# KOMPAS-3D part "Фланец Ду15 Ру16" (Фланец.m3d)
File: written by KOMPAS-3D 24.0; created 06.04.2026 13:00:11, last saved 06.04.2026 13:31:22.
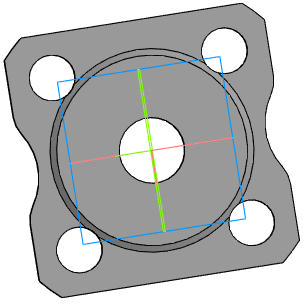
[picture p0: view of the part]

Document properties: Автор: R2D2; Полное имя файла: E:\Работа\Зайцев\Солянка\VSR1-13V-PED-F Клапан запорно-регулирующий DN.ru\DN20\исходные материалы\Фланец.m3d

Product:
- Component [standard]: (unnamed)  | qty 1  | Материал: ВЧ40 ГОСТ 7293-85 (density 7200 kg/m3); Масса: 0.86; additional columns: 20-16-01-1-B-ВЧ40-II-dв 26; Фланец квадратный; ГОСТ 33259-2015
- Part/product: Фланец Ду15 Ру16
    Масса: 0.613226

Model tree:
1. Эскиз:1
2. Элемент выдавливания:1
3. Скругление:1  (with: Ребро.Элемент выдавливания:1)
     Радиус = 10
4. Зеркальный массив:1
5. Экземпляр ( 1 )
6. Экземпляр ( 2 )  (with: Элемент выдавливания:1, Скругление:1)
7. Эскиз:2
8. Элемент выдавливания:2
     Расстояние 1 = -16

Expressions: v108*2
Referenced files in C:\Program Files\ASCON\KOMPAS-3D v24\Libs\PolynomLib\DATA\vault\Methods\Kompas\3D\: PLib_Flange_GOST_33259_1401.m3d
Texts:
  BOSimple***Material:38d6725a-5efe-48e1-b177-a7817acb862a
  BOSimple***PART:1b2ad63d-596a-6bbf-2099-e0277464e9a7***SHORTLOC:B6A6_23E38AE8DB154823[II;1;Квадратный;20;16;26;0;ВЧ40 ГОСТ 7293-85]
  Ch34
  Плоскость XY.Начало координат
  Ось Z.Начало координат
  Плоскость ZY.Начало координат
